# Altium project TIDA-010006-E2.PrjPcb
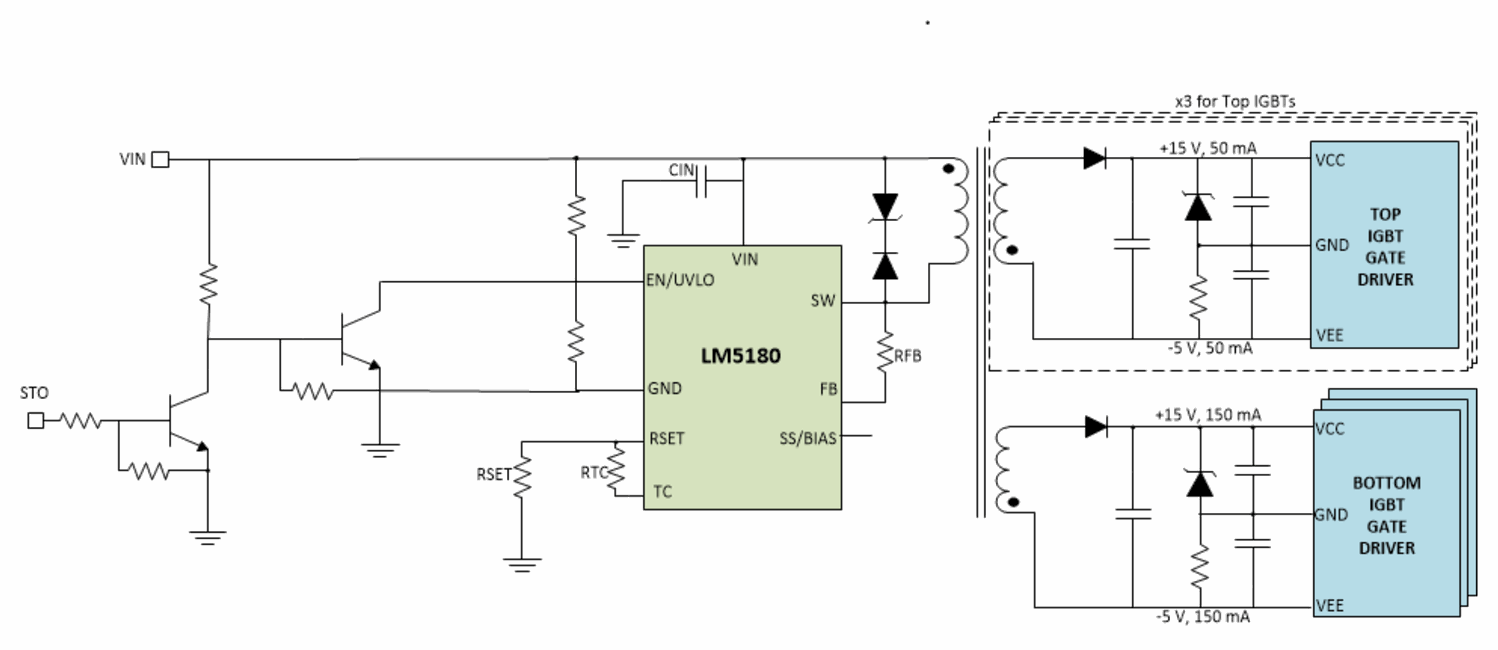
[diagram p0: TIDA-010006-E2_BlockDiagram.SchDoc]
CopyrightYear: 2019; PCB_Layout: Avinash N; PCB_Rev: E2; PRJ_Customer: Public Release; PRJ_Engineer: Vaibhavi; PRJ_Number: TIDA-010006; PRJ_Title: Isolated IGBT Gate-Drive Power Supply Reference Design; SCH_Rev: E2; TechSupport: http://www.ti.com/support; TID: 010006
3 sheets, 90 parts. Net scope: global (net labels, ports and power ports of the same name join across sheets).
Board file: TIDA-010006-E2.PcbDoc
Sheets:
  TIDA-010006-E2_BlockDiagram.SchDoc
  TIDA-010006-E2_Refresh_BlankSheet.SchDoc
  TIDA-010006-E2_EVM_Hardware.SchDoc

## Sheet TIDA-010006-E2_BlockDiagram.SchDoc
size 431 x 279 mm; Date: Not shown in title block; ApprovedBy: Not shown in title block; CheckedBy: Not shown in title block; Author: Not shown in title block; CompanyName: Not shown in title block; Engineer: Not shown in title block; Organization: Not shown in title block; Address1: Not shown in title block; Address2: Not shown in title block; Address3: Not shown in title block; Address4: Not shown in title block; DocumentNumber: 1; Revision: Use project parameter SCH_Rev; SheetNumber: 1; SheetTotal: 3; PageSetup: Record=PageOptions¦CenterHorizontal=True¦CenterVertical=True¦PrintScale=1.00¦XCorrection=1.00¦YCorrection=1.00¦PrintKind=0¦BorderSize=5000000¦LeftOffset=0¦BottomOffset=0¦Orientation=2¦PaperLength=1000¦PaperWidth=1000¦Scale=100¦PaperSource=15¦PrintQuality=600¦MediaType=1¦DitherType=10¦PaperKind=Letter¦PrintScaleMode=1

## Sheet TIDA-010006-E2_Refresh_BlankSheet.SchDoc
size 431 x 279 mm; Date: Not shown in title block; ApprovedBy: Not shown in title block; CheckedBy: Not shown in title block; Author: Not shown in title block; CompanyName: Not shown in title block; Engineer: Not shown in title block; Organization: Not shown in title block; Address1: Not shown in title block; Address2: Not shown in title block; Address3: Not shown in title block; Address4: Not shown in title block; DocumentNumber: 1; Revision: Use project parameter SCH_Rev; SheetNumber: 2; SheetTotal: 3; PageSetup: Record=PageOptions¦CenterHorizontal=True¦CenterVertical=True¦PrintScale=1.00¦XCorrection=1.00¦YCorrection=1.00¦PrintKind=0¦BorderSize=5000000¦LeftOffset=0¦BottomOffset=0¦Orientation=2¦PaperLength=1000¦PaperWidth=1000¦Scale=100¦PaperSource=15¦PrintQuality=600¦MediaType=1¦DitherType=10¦PaperKind=Letter¦PrintScaleMode=1
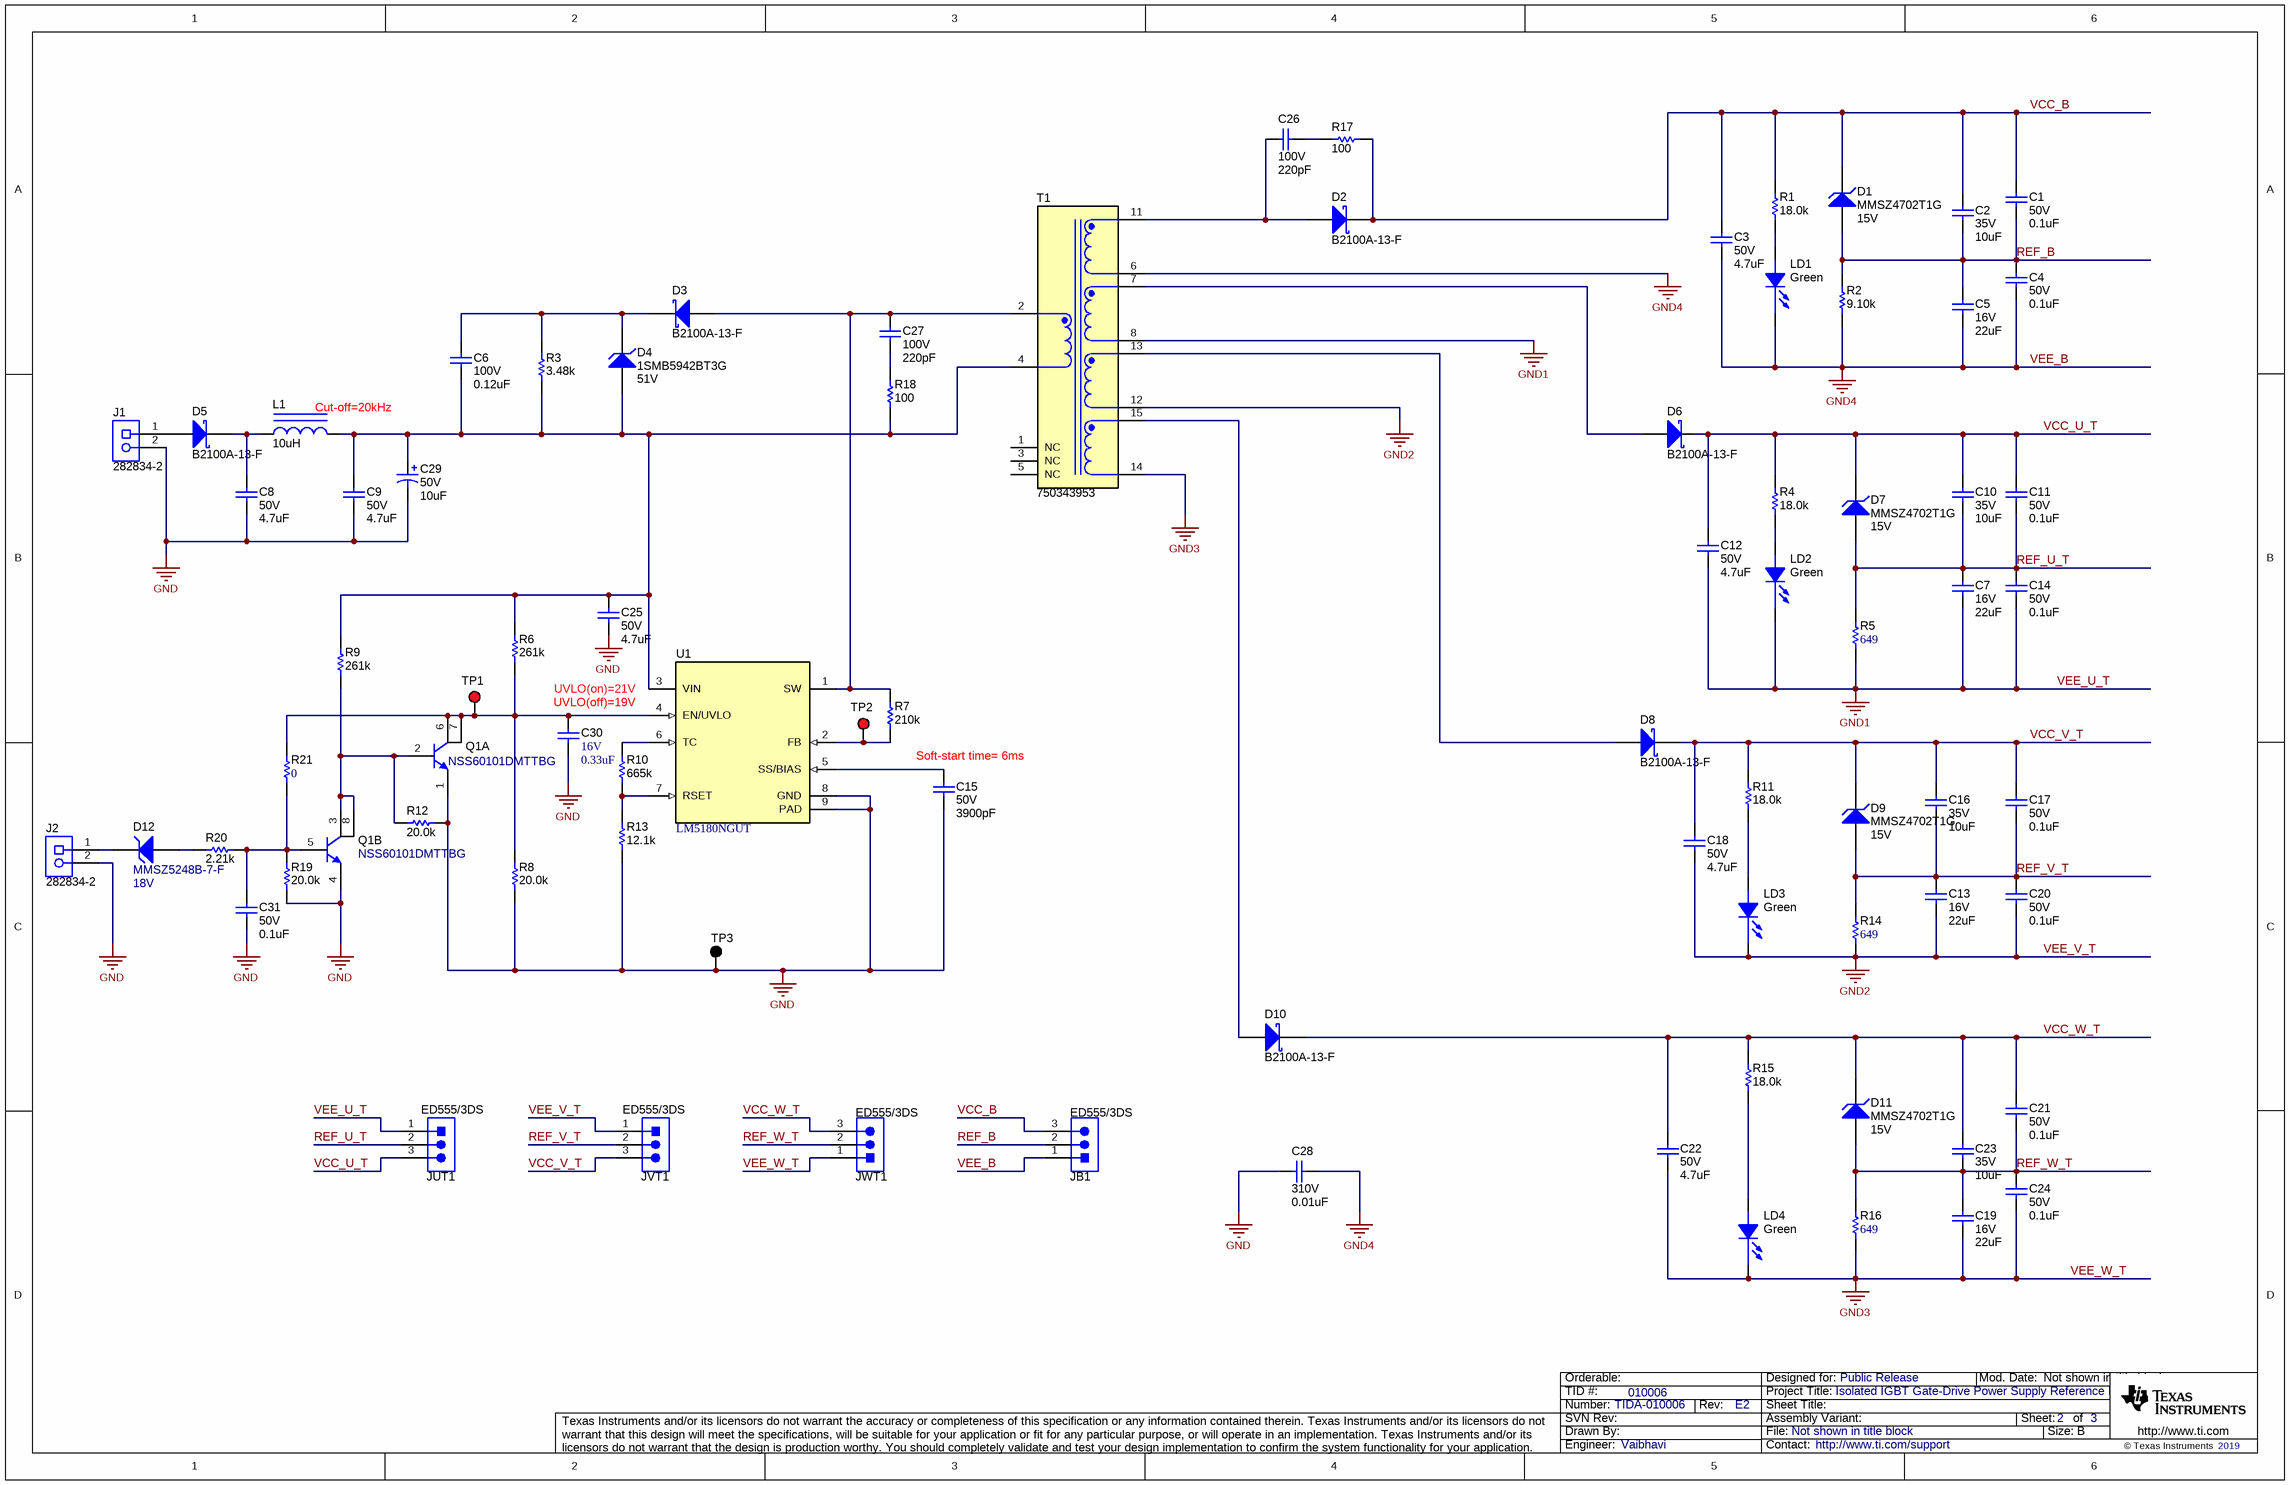
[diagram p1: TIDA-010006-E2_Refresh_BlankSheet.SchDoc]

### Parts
C1  VDC_V: 50V  ValueDisplayed: 0.1uF  [0805_HV]  (hidden comment: UMK212B7104KG-T)
C2  VDC_V: 35V  ValueDisplayed: 10uF  [1206]  (hidden comment: GMK316AB7106KL)
C3  VDC_V: 50V  ValueDisplayed: 4.7uF  [1206_180]  (hidden comment: C3216X7R1H475K160AC)
C4  VDC_V: 50V  ValueDisplayed: 0.1uF  [0805_HV]  (hidden comment: UMK212B7104KG-T)
C5  VDC_V: 16V  ValueDisplayed: 22uF  [1206]  (hidden comment: EMK316BB7226ML-T)
C6  VDC_V: 100V  ValueDisplayed: 0.12uF  [0805_HV]  (hidden comment: C0805C124K1RACTU)
C7  VDC_V: 16V  ValueDisplayed: 22uF  [1206]  (hidden comment: EMK316BB7226ML-T)
C8  VDC_V: 50V  ValueDisplayed: 4.7uF  [1206_180]  (hidden comment: C3216X7R1H475K160AC)
C9  VDC_V: 50V  ValueDisplayed: 4.7uF  [1206_180]  (hidden comment: C3216X7R1H475K160AC)
C10  VDC_V: 35V  ValueDisplayed: 10uF  [1206]  (hidden comment: GMK316AB7106KL)
C11  VDC_V: 50V  ValueDisplayed: 0.1uF  [0805_HV]  (hidden comment: UMK212B7104KG-T)
C12  VDC_V: 50V  ValueDisplayed: 4.7uF  [1206_180]  (hidden comment: C3216X7R1H475K160AC)
C13  VDC_V: 16V  ValueDisplayed: 22uF  [1206]  (hidden comment: EMK316BB7226ML-T)
C14  VDC_V: 50V  ValueDisplayed: 0.1uF  [0805_HV]  (hidden comment: UMK212B7104KG-T)
C15  VDC_V: 50V  ValueDisplayed: 3900pF  [0603]  (hidden comment: GRM188R71H392KA01D)
C16  VDC_V: 35V  ValueDisplayed: 10uF  [1206]  (hidden comment: GMK316AB7106KL)
C17  VDC_V: 50V  ValueDisplayed: 0.1uF  [0805_HV]  (hidden comment: UMK212B7104KG-T)
C18  VDC_V: 50V  ValueDisplayed: 4.7uF  [1206_180]  (hidden comment: C3216X7R1H475K160AC)
C19  VDC_V: 16V  ValueDisplayed: 22uF  [1206]  (hidden comment: EMK316BB7226ML-T)
C20  VDC_V: 50V  ValueDisplayed: 0.1uF  [0805_HV]  (hidden comment: UMK212B7104KG-T)
C21  VDC_V: 50V  ValueDisplayed: 0.1uF  [0805_HV]  (hidden comment: UMK212B7104KG-T)
C22  VDC_V: 50V  ValueDisplayed: 4.7uF  [1206_180]  (hidden comment: C3216X7R1H475K160AC)
C23  VDC_V: 35V  ValueDisplayed: 10uF  [1206]  (hidden comment: GMK316AB7106KL)
C24  VDC_V: 50V  ValueDisplayed: 0.1uF  [0805_HV]  (hidden comment: UMK212B7104KG-T)
C25  VDC_V: 50V  ValueDisplayed: 4.7uF  [1206_180]  (hidden comment: C3216X7R1H475K160AC)
C26  VDC_V: 100V  ValueDisplayed: 220pF  [0603]  (hidden comment: GRM188R72A221KA01D)
C27  VDC_V: 100V  ValueDisplayed: 220pF  [0603]  (hidden comment: GRM188R72A221KA01D)
C28  VDC_V: 310V  ValueDisplayed: 0.01uF  [WCAP-FTXX_P10PL20_13x5x11]  (hidden comment: 890334023006)
C29  VDC_V: 50V  ValueDisplayed: 10uF  [CAPSMT_62_E55]  (hidden comment: EMVA500ADA100ME55G)
C30  VDC_V: 16V  ValueDisplayed: 0.33uF  [0805_HV]  (hidden comment: 0805YC334KAT2A)
C31  VDC_V: 50V  ValueDisplayed: 0.1uF  [0805_HV]  (hidden comment: UMK212B7104KG-T)
D1  MMSZ4702T1G  value 15V  [SOD-123]
D2  B2100A-13-F  [SMA]
D3  B2100A-13-F  [SMA]
D4  1SMB5942BT3G  value 51V  [SMB]
D5  B2100A-13-F  [SMA]
D6  B2100A-13-F  [SMA]
D7  MMSZ4702T1G  value 15V  [SOD-123]
D8  B2100A-13-F  [SMA]
D9  MMSZ4702T1G  value 15V  [SOD-123]
D10  B2100A-13-F  [SMA]
D11  MMSZ4702T1G  value 15V  [SOD-123]
D12  MMSZ5248B-7-F  value 18V  [SOD-123]
J1  282834-2  [TEC_282834-2]
J2  282834-2  [TEC_282834-2]
JB1  ED555/3DS  [TERM_BLK_ED555-3DS]
JUT1  ED555/3DS  [TERM_BLK_ED555-3DS]
JVT1  ED555/3DS  [TERM_BLK_ED555-3DS]
JWT1  ED555/3DS  [TERM_BLK_ED555-3DS]
L1  ValueDisplayed: 10uH  [WE-TPC-M1]  (hidden comment: 744042100)
LD1  value Green  [LG L29K_GREEN]  (hidden comment: LED_LG L29K-G2J1-24-Z)
LD2  value Green  [LG L29K_GREEN]  (hidden comment: LED_LG L29K-G2J1-24-Z)
LD3  value Green  [LG L29K_GREEN]  (hidden comment: LED_LG L29K-G2J1-24-Z)
LD4  value Green  [LG L29K_GREEN]  (hidden comment: LED_LG L29K-G2J1-24-Z)
Q1  NSS60101DMTTBG  [DFN2x2MM_6L]  (parts A,B of 2)
R1  ValueDisplayed: 18.0k  [0603]  (hidden comment: RC0603FR-0718KL)
R2  ValueDisplayed: 9.10k  [0603]  (hidden comment: RC0603FR-079K1L)
R3  ValueDisplayed: 3.48k  [1206]  (hidden comment: ERJ-8ENF3481V)
R4  ValueDisplayed: 18.0k  [0603]  (hidden comment: RC0603FR-0718KL)
R5  ValueDisplayed: 649  [0805_HV]  (hidden comment: RC0805FR-07649RL)
R6  ValueDisplayed: 261k  [0603]  (hidden comment: RT0603BRD07261KL)
R7  ValueDisplayed: 210k  [0603]  (hidden comment: RC0603FR-07210KL)
R8  ValueDisplayed: 20.0k  [0603]  (hidden comment: RC0603FR-0720KL)
R9  ValueDisplayed: 261k  [0603]  (hidden comment: RT0603BRD07261KL)
R10  ValueDisplayed: 665k  [0603]  (hidden comment: RC0603FR-07665KL)
R11  ValueDisplayed: 18.0k  [0603]  (hidden comment: RC0603FR-0718KL)
R12  ValueDisplayed: 20.0k  [0603]  (hidden comment: RC0603FR-0720KL)
R13  ValueDisplayed: 12.1k  [0603]  (hidden comment: RT0603DRE0712K1L)
R14  ValueDisplayed: 649  [0805_HV]  (hidden comment: RC0805FR-07649RL)
R15  ValueDisplayed: 18.0k  [0603]  (hidden comment: RC0603FR-0718KL)
R16  ValueDisplayed: 649  [0805_HV]  (hidden comment: RC0805FR-07649RL)
R17  ValueDisplayed: 100  [0805_HV]  (hidden comment: RG2012P-101-B-T5)
R18  ValueDisplayed: 100  [0805_HV]  (hidden comment: RG2012P-101-B-T5)
R19  ValueDisplayed: 20.0k  [0603]  (hidden comment: RC0603FR-0720KL)
R20  ValueDisplayed: 2.21k  [0603]  (hidden comment: RG1608P-2211-B-T5)
R21  ValueDisplayed: 0  [5106]  (hidden comment: 5106)
T1  750343953  [Wurth_EPW15_5996]
TP1  5000  [Keystone5000]  (value not drawn)
TP2  5000  [Keystone5000]  (value not drawn)
TP3  5001  [Keystone5001]  (value not drawn)
U1  LM5180NGUT  [NGU0008C]

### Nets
GND: C8.2 C9.2 C15.2 C25.2 C28.2 C29.2(-) C30.2 C31.2 J1.2 J2.2 Q1.1(E) Q1.4(E) R8.1 R12.1 R13.1 R19.2 TP3.1 U1.8(GND) U1.9(PAD)
VEE_B: C3.2 C4.2 C5.2 C28.1 JB1.1 LD1.1(C) R2.1 T1.6  [also labelled GND4]
VEE_U_T: C7.2 C12.2 C14.2 JUT1.1 LD2.1(C) R5.1 T1.8  [also labelled GND1]
VEE_V_T: C13.2 C18.2 C20.2 JVT1.1 LD3.1(C) R14.1 T1.12  [also labelled GND2]
VEE_W_T: C19.2 C22.2 C24.2 JWT1.1 LD4.1(C) R16.1 T1.14  [also labelled GND3]
REF_B: C1.2 C2.2 C4.1 C5.1 D1.2(A) JB1.2 R2.2
REF_U_T: C7.1 C10.2 C11.2 C14.1 D7.2(A) JUT1.2 R5.2
REF_V_T: C13.1 C16.2 C17.2 C20.1 D9.2(A) JVT1.2 R14.2
REF_W_T: C19.1 C21.2 C23.2 C24.1 D11.2(A) JWT1.2 R16.2
VCC_B: C1.1 C2.1 C3.1 D1.1(K) D2.1(K) JB1.3 R1.2 R17.1
VCC_U_T: C10.1 C11.1 C12.1 D6.1(K) D7.1(K) JUT1.3 R4.2
VCC_V_T: C16.1 C17.1 C18.1 D8.1(K) D9.1(K) JVT1.3 R11.2
VCC_W_T: C21.1 C22.1 C23.1 D10.1(K) D11.1(K) JWT1.3 R15.2
NetC6_1: C6.1 D3.1(K) D4.1(K) R3.2
NetC6_2: C6.2 C9.1 C25.1 C29.1(+) D4.2(A) L1.2 R3.1 R6.2 R9.2 R18.1 T1.4 U1.3(VIN)
NetC8_1: C8.1 D5.1(K) L1.1
NetC15_1: C15.1 U1.5(SS/BIAS)
NetC26_1: C26.1 D2.2(A) T1.11
NetC26_2: C26.2 R17.2
NetC27_1: C27.1 D3.2(A) R7.2 T1.2 U1.1(SW)
NetC27_2: C27.2 R18.2
NetC30_1: C30.1 Q1.6(C) Q1.7(C) R6.1 R8.2 R21.2 TP1.1 U1.4(EN/UVLO)
NetC31_1: C31.1 Q1.5(B) R19.1 R20.1 R21.1
NetD5_2: D5.2(A) J1.1
NetD6_2: D6.2(A) T1.7
NetD8_2: D8.2(A) T1.13
NetD10_2: D10.2(A) T1.15
NetD12_1: D12.1(K) J2.1
NetD12_2: D12.2(A) R20.2
NetLD1_2: LD1.2(A) R1.1
NetLD2_2: LD2.2(A) R4.1
NetLD3_2: LD3.2(A) R11.1
NetLD4_2: LD4.2(A) R15.1
NetQ1_2: Q1.2(B) Q1.3(C) Q1.8(C) R9.1 R12.2
NetR7_1: R7.1 TP2.1 U1.2(FB)
NetR10_1: R10.1 R13.2 U1.7(RSET)
NetR10_2: R10.2 U1.6(TC)

Not connected (* = marked no-connect by the designer): T1 1(NC) 3(NC) 5(NC)

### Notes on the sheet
- (near L1) Cut-off=20kHz
- UVLO(on)=21V
- (near C30) UVLO(off)=19V
- Soft-start time= 6ms

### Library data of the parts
C1 C4 C11 C14 C17 C20 C21 C24 C31 = CMP-0008420-2: CAP, CERM, 0.1 uF, 50 V, +/- 10%, X7R, 0805; Manufacturer: Taiyo Yuden; TaMin_C: -55°C; Polarized: N; SizeAreaWB_mm2: 6.75; Value1: Unknown; U/M: EA; Value: 0.1uF; TaMax_C: 125°C; SizeZ_mm: 1.45; SizeX_mm: 2; SizeY_mm: 1.25; Cap_Case: 0805; SizeArea_mm2: 2.5; CompType: Capacitor; Cap_F: 100nF; AEC Category: Q200
C2 C10 C16 C23 = CMP-0008821-2: CAP, CERM, 10 uF, 35 V, +/- 10%, X7R, 1206; Manufacturer: Taiyo Yuden; TaMin_C: -55°C; Polarized: N; SizeAreaWB_mm2: 10.92; Value1: Unknown; U/M: EA; Value: 10uF; TaMax_C: 125°C; SizeZ_mm: 1.35; SizeX_mm: 3.2; SizeY_mm: 1.6; SizeArea_mm2: 5.12; CompType: Capacitor; Cap_F: 10µF; AEC Category: Q200
C3 C12 C25 = CMP-0008702-2: CAP, CERM, 4.7 uF, 50 V, +/- 10%, X7R, 1206; Manufacturer: TDK; TaMin_C: -55°C; ESR_ohm: 3.158m; Polarized: N; SizeAreaWB_mm2: 10.92; Value1: 0.003158 ohm; U/M: EA; Value: 4.7uF; TaMax_C: 125°C; SizeZ_mm: 1.8; SizeX_mm: 3.2; SizeY_mm: 1.6; SizeArea_mm2: 5.12; Cap_F: 4.7µF; IRMS_A: 4.08379A; AEC Category: Q200
C5 C7 C13 C19 = CMP-0008805-2: CAP, CERM, 22 uF, 16 V, +/- 20%, X7R, 1206_190; Manufacturer: Taiyo Yuden; TaMin_C: -55°C; Polarized: N; SizeAreaWB_mm2: 10.92; Value1: Unknown; U/M: EA; Value: 22uF; TaMax_C: 125°C; SizeZ_mm: 1.9; SizeX_mm: 3.2; SizeY_mm: 1.6; SizeArea_mm2: 5.12; Cap_F: 22µF; AEC Category: Q200
C6 = CMP-0007738-2: CAP, CERM, 0.12 uF, 100 V, +/- 10%, X7R, 0805; Manufacturer: Kemet; TaMin_C: -55°C; ESR_ohm: 0.059; Polarized: N; SizeAreaWB_mm2: 6.75; Value1: 0.059 ohm; U/M: EA; Value: 0.12uF; TaMax_C: 125°C; SizeZ_mm: 1.45; SizeX_mm: 2; SizeY_mm: 1.25; Cap_Case: 0805; SizeArea_mm2: 2.5; CompType: Capacitor; Cap_F: 120nF; IRMS_A: 1.84A; AEC Category: Q200
C8 C9 C18 C22 = CMP-0008702-2: CAP, CERM, 4.7 uF, 50 V, +/- 10%, X7R, 1206; Manufacturer: TDK; TaMin_C: -55°C; ESR_ohm: 3.158m; Polarized: N; SizeAreaWB_mm2: 10.92; Value1: 0.003158 ohm; U/M: EA; Value: 4.7uF; TaMax_C: 125°C; SizeZ_mm: 1.8; SizeX_mm: 3.2; SizeY_mm: 1.6; SizeArea_mm2: 5.12; CompType: Capacitor; Cap_F: 4.7µF; IRMS_A: 4.08379A; AEC Category: Q200
C15 = CMP-0007453-4: CAP, CERM, 3900 pF, 50 V, +/- 10%, X7R, 0603; Manufacturer: MuRata; TaMin_C: -55°C; Polarized: N; SizeAreaWB_mm2: 4.68; Value1: Unknown; U/M: EA; Value: 3900pF; TaMax_C: 125°C; SizeZ_mm: 1; SizeX_mm: 1.6; SizeY_mm: 0.8; SizeArea_mm2: 1.28; CompType: Capacitor; Cap_F: 3.9nF; AEC Category: Q200
C26 = CMP-0007474-4: CAP, CERM, 220 pF, 100 V, +/- 10%, X7R, 0603; Manufacturer: MuRata; TaMin_C: -55°C; Polarized: N; SizeAreaWB_mm2: 4.68; Value1: Unknown; U/M: EA; Value: 220pF; TaMax_C: 125°C; SizeZ_mm: 1; SizeX_mm: 1.6; SizeY_mm: 0.8; SizeArea_mm2: 1.28; AEC Category: Q200
C27 = CMP-0007474-4: CAP, CERM, 220 pF, 100 V, +/- 10%, X7R, 0603; Manufacturer: MuRata; TaMin_C: -55°C; Polarized: N; SizeAreaWB_mm2: 4.68; Value1: Unknown; U/M: EA; Value: 220pF; TaMax_C: 125°C; SizeZ_mm: 1; SizeX_mm: 1.6; SizeY_mm: 0.8; SizeArea_mm2: 1.28; CompType: Capacitor; AEC Category: Q200
C28 = CMP-0012317-3: CAP, Film, 0.01 uF, 310 V, +/- 10%, TH; Manufacturer: Wurth Elektronik; TaMin_C: -40°C; Polarized: N; Value1: Unknown; Value: 0.01uF; TaMax_C: 105°C; Cap_Case: 13x5x11mm; Cap_F: 10nF; AEC Category: Q200
C29 = CMP-0011235-3: CAP, AL, 10 uF, 50 V, +/- 20%, SMD; Manufacturer: Chemi-Con; TaMin_C: -40°C; Polarized: Y; SizeAreaWB_mm2: 53.29; Value1: Unknown; U/M: EA; Value: 10uF; TaMax_C: 85°C; SizeZ_mm: 5.2; SizeX_mm: 5.3; Cap_Case: E55; SizeArea_mm2: 28.09; CompType: Capacitor; Cap_F: 10µF; IRMS_A: 30mA; AEC Category: Q200
C30 = CMP-0007673-2: CAP, CERM, 0.33 uF, 16 V, +/- 10%, X7R, 0805; Manufacturer: AVX; TaMin_C: -55°C; ESR_ohm: 0.013; Polarized: N; SizeAreaWB_mm2: 6.75; Value1: 0.013 ohm; U/M: EA; Value: 0.33uF; TaMax_C: 125°C; SizeZ_mm: 1.45; SizeX_mm: 2; SizeY_mm: 1.25; Cap_Case: 0805; SizeArea_mm2: 2.5; Cap_F: 330nF; AEC Category: Q200
D1 D7 D9 D11 = CMP-0005745-2: Diode, Zener, 15 V, 500 mW, SOD-123; Manufacturer: ON Semiconductor; Power_W: 500mW; SizeAreaWB_mm2: 13.095; Value1: 0.5W; RJA_CperW: 340; U/M: EA; SizeZ_mm: 1.35; SizeX_mm: 3.85; SizeY_mm: 1.7; SizeArea_mm2: 6.545; AEC Category: Q101
D2 D3 D5 D6 D8 D10 = CMP-0081099-1: Diode, Schottky, 100 V, 2 A, SMA; Manufacturer: Diodes Inc.; SizeAreaWB_mm2: 37.3428; Vr_V: 100V; SizeArea_mm2: 16.3228; AEC Qualified: N; TJmax_C: 125°C; AEC Category: Q101; Value: 100V; SizeZ_mm: 2.87; Io_A: 2A; Vf_V: 7.9dV; SizeY_mm: 2.92; Value2: 0.79V; SizeX_mm: 5.59
D4 = CMP-0005610-2: Diode, Zener, 51 V, 550 mW, SMB; Manufacturer: ON Semiconductor; Power_W: 550mW; SizeAreaWB_mm2: 44.156; Value1: 0.55W; RJA_CperW: 226; U/M: EA; SizeZ_mm: 2.6; SizeX_mm: 5.6; SizeY_mm: 3.81; SizeArea_mm2: 21.336; AEC Category: Q101
D12 = CMP-0005755-4: Diode, Zener, 18 V, 500 mW, SOD-123; Manufacturer: Diodes Inc.; SizeAreaWB_mm2: 13.095; RJA_CperW: 350; SizeArea_mm2: 6.545; Power_W: 500mW; SizeX_mm: 3.85; SizeY_mm: 1.7; AEC Category: Q101; Value1: 0.5W; SizeZ_mm: 1.35
J1 J2 = CMP-0054974-1: Terminal Block, 2x1, 2.54mm, TH; Manufacturer: TE Connectivity; CNHeader: FALSE; Green_Lifecycle: Active; Green_REACh: Passed; CT: TRUE
JB1 JUT1 JVT1 JWT1 = ED555/3DS: Terminal Block, 6A, 3.5mm Pitch, 3-Pos, TH; Manufacturer: On-Shore Technology; SymbolCreator: a0799628; CompType: Connector; U/M: EA
L1 = CMP-0063804-1: Inductor, Shielded Drum Core, Ferrite, 10 uH, 1 A, 0.12 ohm, SMD; Manufacturer: Wurth Elektronik; Isat: 1A @ 35% inductance drop; Irms: 1.3A @ 30C rise; Green_Lifecycle: Active; SizeAreaWB_mm2: 33.64; DCR_ohm: 1.2d; Green_REACh: Passed; Value: 10uH; Imax_A: 1A; SizeZ_mm: 1.8; SizeX_mm: 4.8; SizeArea_mm2: 23.04; Ind_H: 10µH; AEC Category: Q200
LD1-LD4 = LED_LG L29K-G2J1-24-Z: LED SmartLED Green 570NM; Manufacturer: OSRAM; SymbolCreator: x0120606
Q1 = CMP-0000492-2: Transistor, Dual NPN, 60 V, 1 A, AEC-Q101, 6-WDFN; Manufacturer: ON Semiconductor; TaMax_C: 150°C; Value1: 1 A; Vcesat1_V: 63mV; SizeX_mm: 2; TaMin_C: -55°C; IcRated_A: 1A; CompType: BJT; SizeZ_mm: 0.8; AEC Qualified: Y; Value: 60 V; SizeArea_mm2: 4; Vceo_V: 60V; PNP: 0; AEC Category: Q101; SizeAreaWB_mm2: 9; U/M: EA
R1 R4 R11 R15 = CMP-0022852-5: RES, 18.0 k, 1%, 0.1 W, 0603; Manufacturer: Yageo; Power_W: 100mW; TempCo: 100 ppm/C; Value_Code: 18k0; Value: 18.0k; Res_ohm: 18k; SizeX_mm: 1.6; SizeY_mm: 0.8; SizeZ_mm: 1; Value2: 0.1W; SizeArea_mm2: 1.28; AEC Qualified: N; VDC_V: 75V; AEC Category: Q200; SizeAreaWB_mm2: 4.68
R2 = CMP-0023333-5: RES, 9.10 k, 1%, 0.1 W, 0603; Manufacturer: Yageo; Power_W: 100mW; TempCo: 100 ppm/C; Value_Code: 9k10; Value: 9.10k; Res_ohm: 9.1k; SizeX_mm: 1.6; SizeY_mm: 0.8; SizeZ_mm: 1; Value2: 0.1W; SizeArea_mm2: 1.28; CompType: Resistor; AEC Qualified: N; VDC_V: 75V; AEC Category: Q200; SizeAreaWB_mm2: 4.68
R3 = CMP-0017552-2: RES, 3.48 k, 1%, 0.25 W, 1206; Manufacturer: Panasonic; Power_W: 250mW; TempCo: 100 ppm/C; Value_Code: 3k48; U/M: EA; Value: 3.48k; EIA_Code: E96; SizeX_mm: 3.2; SizeY_mm: 1.6; SizeZ_mm: 1.35; Value2: 0.25W; SizeArea_mm2: 5.12; CompType: Resistor; VDC_V: 200V; AEC Category: Q200
R5 R14 R16 = CMP-0082503-1: RES, 649, 1%, 0.125 W, 0805; Manufacturer: Yageo; Value_Code: 649R; SizeAreaWB_mm2: 6.75; SizeArea_mm2: 2.5; AEC Qualified: N; AEC Category: Q200; Value: 649; SizeZ_mm: 1.45; EIA_Code: E96; TempCo: 100 ppm/C; Power_W: 125mW; VDC_V: 150V; SizeY_mm: 1.25; Value2: 0.125W; SizeX_mm: 2
R6 R9 = CMP-0024008-3: RES, 261 k, 0.1%, 0.1 W, 0603; Manufacturer: Yageo America; Power_W: 100mW; TempCo: 25 ppm/C; U/M: EA; Value: 261k; EIA_Code: E192; SizeX_mm: 1.6; SizeY_mm: 0.8; SizeZ_mm: 1; Value2: 0.1W; SizeArea_mm2: 1.28; CompType: Resistor; VDC_V: 75V; AEC Category: Q200
R7 = CMP-0022909-4: RES, 210 k, 1%, 0.1 W, 0603; Manufacturer: Yageo; Power_W: 100mW; TempCo: 100 ppm/C; Value: 210k; EIA_Code: E96; SizeX_mm: 1.6; SizeY_mm: 0.8; SizeZ_mm: 1; Value2: 0.1W; SizeArea_mm2: 1.28; CompType: Resistor; AEC Qualified: N; VDC_V: 75V; AEC Category: Q200; SizeAreaWB_mm2: 4.68
R8 = CMP-0022906-3: RES, 20.0 k, 1%, 0.1 W, 0603; Manufacturer: Yageo America; Power_W: 100mW; TempCo: 200 ppm/C; Value_Code: 20k0; U/M: EA; Value: 20.0k; EIA_Code: E96; Res_ohm: 20k; SizeX_mm: 1.6; SizeY_mm: 0.8; SizeZ_mm: 1; Value2: 0.1W; SizeArea_mm2: 1.28; VDC_V: 150V; AEC Category: Q200
R10 = CMP-0023230-4: RES, 665 k, 1%, 0.1 W, 0603; Manufacturer: Yageo; Power_W: 100mW; TempCo: 100 ppm/C; Value: 665k; EIA_Code: E96; SizeX_mm: 1.6; SizeY_mm: 0.8; SizeZ_mm: 1; Value2: 0.1W; SizeArea_mm2: 1.28; AEC Qualified: N; VDC_V: 75V; AEC Category: Q200; SizeAreaWB_mm2: 4.68
R12 R19 = CMP-0022906-3: RES, 20.0 k, 1%, 0.1 W, 0603; Manufacturer: Yageo America; Power_W: 100mW; TempCo: 200 ppm/C; Value_Code: 20k0; U/M: EA; Value: 20.0k; EIA_Code: E96; Res_ohm: 20k; SizeX_mm: 1.6; SizeY_mm: 0.8; SizeZ_mm: 1; Value2: 0.1W; SizeArea_mm2: 1.28; CompType: Resistor; VDC_V: 150V; AEC Category: Q200
R13 = CMP-0024637-3: RES, 12.1 k, 0.5%, 0.1 W, 0603; Manufacturer: Yageo America; Power_W: 100mW; TempCo: 50 ppm/C; Value_Code: 12k1; U/M: EA; Value: 12.1k; EIA_Code: E192; SizeX_mm: 1.6; SizeY_mm: 0.8; SizeZ_mm: 1; Value2: 0.1W; SizeArea_mm2: 1.28; VDC_V: 75V; AEC Category: Q200
R17 R18 = CMP-0018851-2: RES, 100, 0.1%, 0.125 W, 0805; Manufacturer: Susumu Co Ltd; Power_W: 125mW; TempCo: 25 ppm/C; Value_Code: 100R; U/M: EA; Value: 100; EIA_Code: E192; SizeX_mm: 2; SizeY_mm: 1.25; SizeZ_mm: 1.45; Value2: 0.125W; SizeArea_mm2: 2.5; VDC_V: 100V; AEC Category: Q200
R20 = CMP-0023469-3: RES, 2.21 k, 0.1%, 0.1 W, 0603; Manufacturer: Susumu Co Ltd; Power_W: 100mW; TempCo: 25 ppm/C; Value_Code: 2k21; U/M: EA; Value: 2.21k; EIA_Code: E192; SizeX_mm: 1.6; SizeY_mm: 0.8; SizeZ_mm: 1; Value2: 0.1W; SizeArea_mm2: 1.28; CompType: Resistor; VDC_V: 75V; AEC Category: Q200
R21 = CMP-0020833-2: RES, 0, 1%, 0.5 W, 0805; Manufacturer: Keystone; Power_W: 500mW; TempCo: ppm/C; U/M: EA; Value: 0; SizeX_mm: 2; SizeY_mm: 1.25; SizeZ_mm: 0.84; Value2: 0.5W; SizeArea_mm2: 2.5; AEC Qualified: N; AEC Category: Q200
T1 = CMP-0082101-1: Transformer, 47 uH, TH; Manufacturer: Wurth Elektronik; SizeAreaWB_mm2: 426.57; SizeArea_mm2: 346.97; AEC Qualified: N; Ns2toNp: 1; Lp: 47; AEC Category: Q200; Value: 47uH; SizeZ_mm: 23.3; Ind_H: 47µH; SizeY_mm: 15.7; SizeX_mm: 22.1
TP1 TP2 = CMP-0055137-1: Test Point, Miniature, Red, TH; Manufacturer: Keystone; CNHeader: FALSE; Green_Lifecycle: Active; Green_REACh: Passed; ContactFinish: Silver; CT: TRUE
TP3 = CMP-0055138-1: Test Point, Miniature, Black, TH; Manufacturer: Keystone; CNHeader: FALSE; Green_Lifecycle: Active; Green_REACh: Passed; ContactFinish: Silver; CT: TRUE
U1 = CMP-0084792-1: 70-VIN PSR Flyback DC/DC Converter With 100-V, 1.5-A Integrated Power MOSFET, NGU0008C (WSON-8); Alternate PartNumber: LM5180NGUR; Manufacturer: Texas Instruments; SizeArea_mm2: 16; SizeY_mm: 4; AEC Category: Q200; SizeAreaWB_mm2: 25; SizeZ_mm: 0.8; AEC Qualified: N; CompType: IC

## Sheet TIDA-010006-E2_EVM_Hardware.SchDoc
size 431 x 279 mm; Date: Not shown in title block; ApprovedBy: Not shown in title block; CheckedBy: Not shown in title block; Author: Not shown in title block; CompanyName: Not shown in title block; Engineer: Not shown in title block; Organization: Not shown in title block; Address1: Not shown in title block; Address2: Not shown in title block; Address3: Not shown in title block; Address4: Not shown in title block; DocumentNumber: 1; Revision: Use project parameter SCH_Rev; SheetNumber: 3; SheetTotal: 3; PageSetup: Record=PageOptions¦CenterHorizontal=True¦CenterVertical=True¦PrintScale=1.00¦XCorrection=1.00¦YCorrection=1.00¦PrintKind=0¦BorderSize=5000000¦LeftOffset=0¦BottomOffset=0¦Orientation=2¦PaperLength=1000¦PaperWidth=1000¦Scale=100¦PaperSource=15¦PrintQuality=600¦MediaType=1¦DitherType=10¦PaperKind=Letter¦PrintScaleMode=1
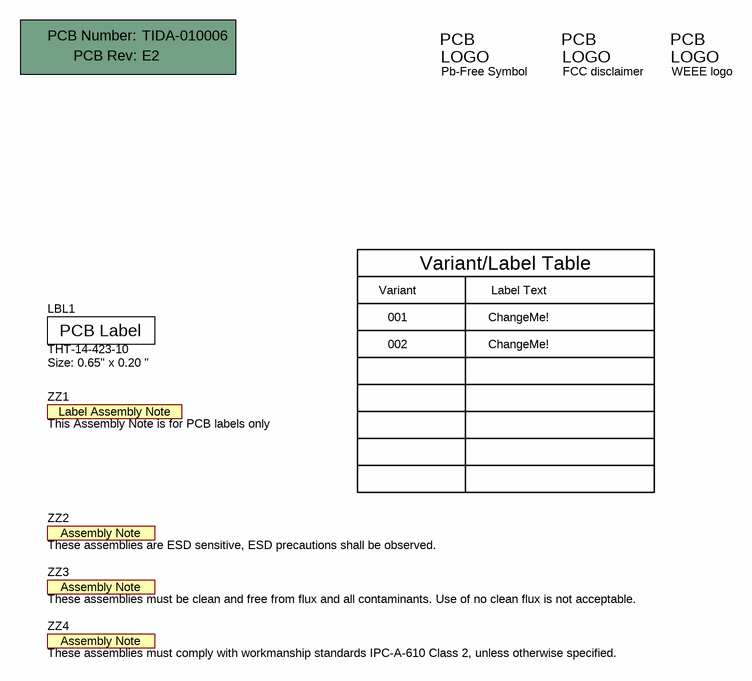
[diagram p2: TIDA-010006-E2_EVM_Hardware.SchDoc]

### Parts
!PCB  Printed Circuit Board  (value not drawn)  (mechanical)
LBL1  THT-14-423-10  Note: Size: 0.65" x 0.20 "  [Label_650x200]
Logo2  Pb-Free Symbol  [Pb-Free_Overlay_Small]  (no BOM)
Logo3  FCC disclaimer  [FCC_disclaimer]  (no BOM)
Logo4  WEEE logo  [WEEE_Minimum]  (no BOM)
ZZ1  This Assembly Note is for PCB labels only  [AssemblyNoteLabel]  (no BOM)
ZZ2  These assemblies are ESD sensitive, ESD precautions shall be observed.  [AssemblyNote]  (no BOM)
ZZ3  These assemblies must be clean and free from flux and all contaminants. Use of no clean flux is not acceptable.  [AssemblyNote]  (no BOM)
ZZ4  These assemblies must comply with workmanship standards IPC-A-610 Class 2, unless otherwise specified.  [AssemblyNote]  (no BOM)

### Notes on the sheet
- Variant
- Variant/Label Table
- Label Text
- 001
- 002
- ChangeMe!

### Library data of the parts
!PCB = CMP-0003618-2: Manufacturer: Any; PartNumber: TIDA-010006
LBL1 = CMP-0003625-1: Thermal Transfer Printable Labels, 0.650" W x 0.200" H - 10,000 per roll; Manufacturer: Brady; CompType: Label
Logo2 = CMP-0074839-1: SymbolCreator: a0412235; Library Reference: Logo
Logo3 = CMP-0074847-1: FCC_disclaimer; Library Reference: Logo
Logo4 = CMP-0074769-1
ZZ1 = CMP-0003616-3
ZZ2 = CMP-0077236-1
ZZ3 = CMP-0077237-1
ZZ4 = CMP-0077238-1

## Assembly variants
001: not fitted C6 C15 C28 R3 R?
